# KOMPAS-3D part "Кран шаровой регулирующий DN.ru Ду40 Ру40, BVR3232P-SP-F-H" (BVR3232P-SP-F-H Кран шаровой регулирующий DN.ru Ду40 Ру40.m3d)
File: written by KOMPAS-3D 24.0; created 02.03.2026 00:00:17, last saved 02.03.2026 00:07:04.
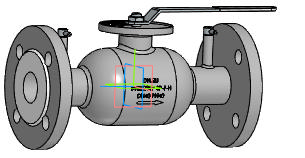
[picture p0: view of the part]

Document properties: Автор: Максим; Полное имя файла: BVR3232P-SP-F-H  - Кран шаровой регулирующий DN.ru  Ду40 Ру40.cdw

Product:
- Body: Тело 1  | qty 1
    Масса: 10.980714
- Part/product: Кран шаровой регулирующий DN.ru Ду40 Ру40  | designation BVR3232P-SP-F-H
    Масса: 8.1
    Раздел спецификации: Прочие изделия
    Форматы листов документа: A2
    Примечание: D160-69421

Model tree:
1. Операция без истории:1

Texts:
  BVR3232P-SP-F-H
